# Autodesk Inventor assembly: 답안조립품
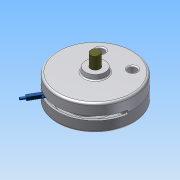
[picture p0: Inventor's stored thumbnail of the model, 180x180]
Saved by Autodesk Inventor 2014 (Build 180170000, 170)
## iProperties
Created: 2015-06
Part Number: 답안조립품
Document SubType Name: Assembly
Designer: Administrator
Author: Administrator
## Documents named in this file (10)
- C:\Documents and Settings\Administrator\바탕 화면\450631V1017\답안조립품.iam
- C:\Documents and Settings\Administrator\바탕 화면\450631V1017\1-본체.ipt
- C:\Documents and Settings\Administrator\바탕 화면\450631V1017\덮개.ipt
- C:\Documents and Settings\Administrator\바탕 화면\450631V1017\슬라이더.ipt
- C:\Documents and Settings\Administrator\바탕 화면\450631V1017\멈춤링.ipt
- C:\Documents and Settings\Administrator\바탕 화면\450631V1017\베어링62_22.ipt
- C:\Documents and Settings\Administrator\바탕 화면\450631V1017\슬라이더2.ipt
- C:\Documents and Settings\Administrator\바탕 화면\450631V1017\축.ipt
- C:\Documents and Settings\Administrator\바탕 화면\450631V1017\평행핀.ipt
- C:\Documents and Settings\Administrator\바탕 화면\450631V1017\M10x35.ipt
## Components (8 placed, 5 different names)
1. 1-본체:1
2. KS B 1336 22 x 1.2:1
3. KS B 2023 62/22 - 22 x 50 x 14:1
4. KS B 2023 62/22 - 22 x 50 x 14:2
5. KS B 1336 22 x 1.2:2
6. KS B 1320 B B 5 x  20:1
7. KS B 1003 - 미터 M 10 x 35:1
8. KS B 1003 - 미터 M 10 x 35:2
